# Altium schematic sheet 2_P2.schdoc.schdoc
size 309 x 223 mm; Symbol: Sheet-Symbol_A4; Device: Sheet-Symbol_A4; Company: Sai Automations; Drawed: EasyEDA Pro; Reviewed: EasyEDA Pro; Version: V0.1; Page Size: A4; @Project Name: SHA-PCB V1.1; @Page Count: 2; @Update Date: 2024-07-18; @Create Date: 2024-01-13; @Schematic Name: Schematic1; Part Number: JLCPCB-002; @Page No: 2; @Page Name: P2
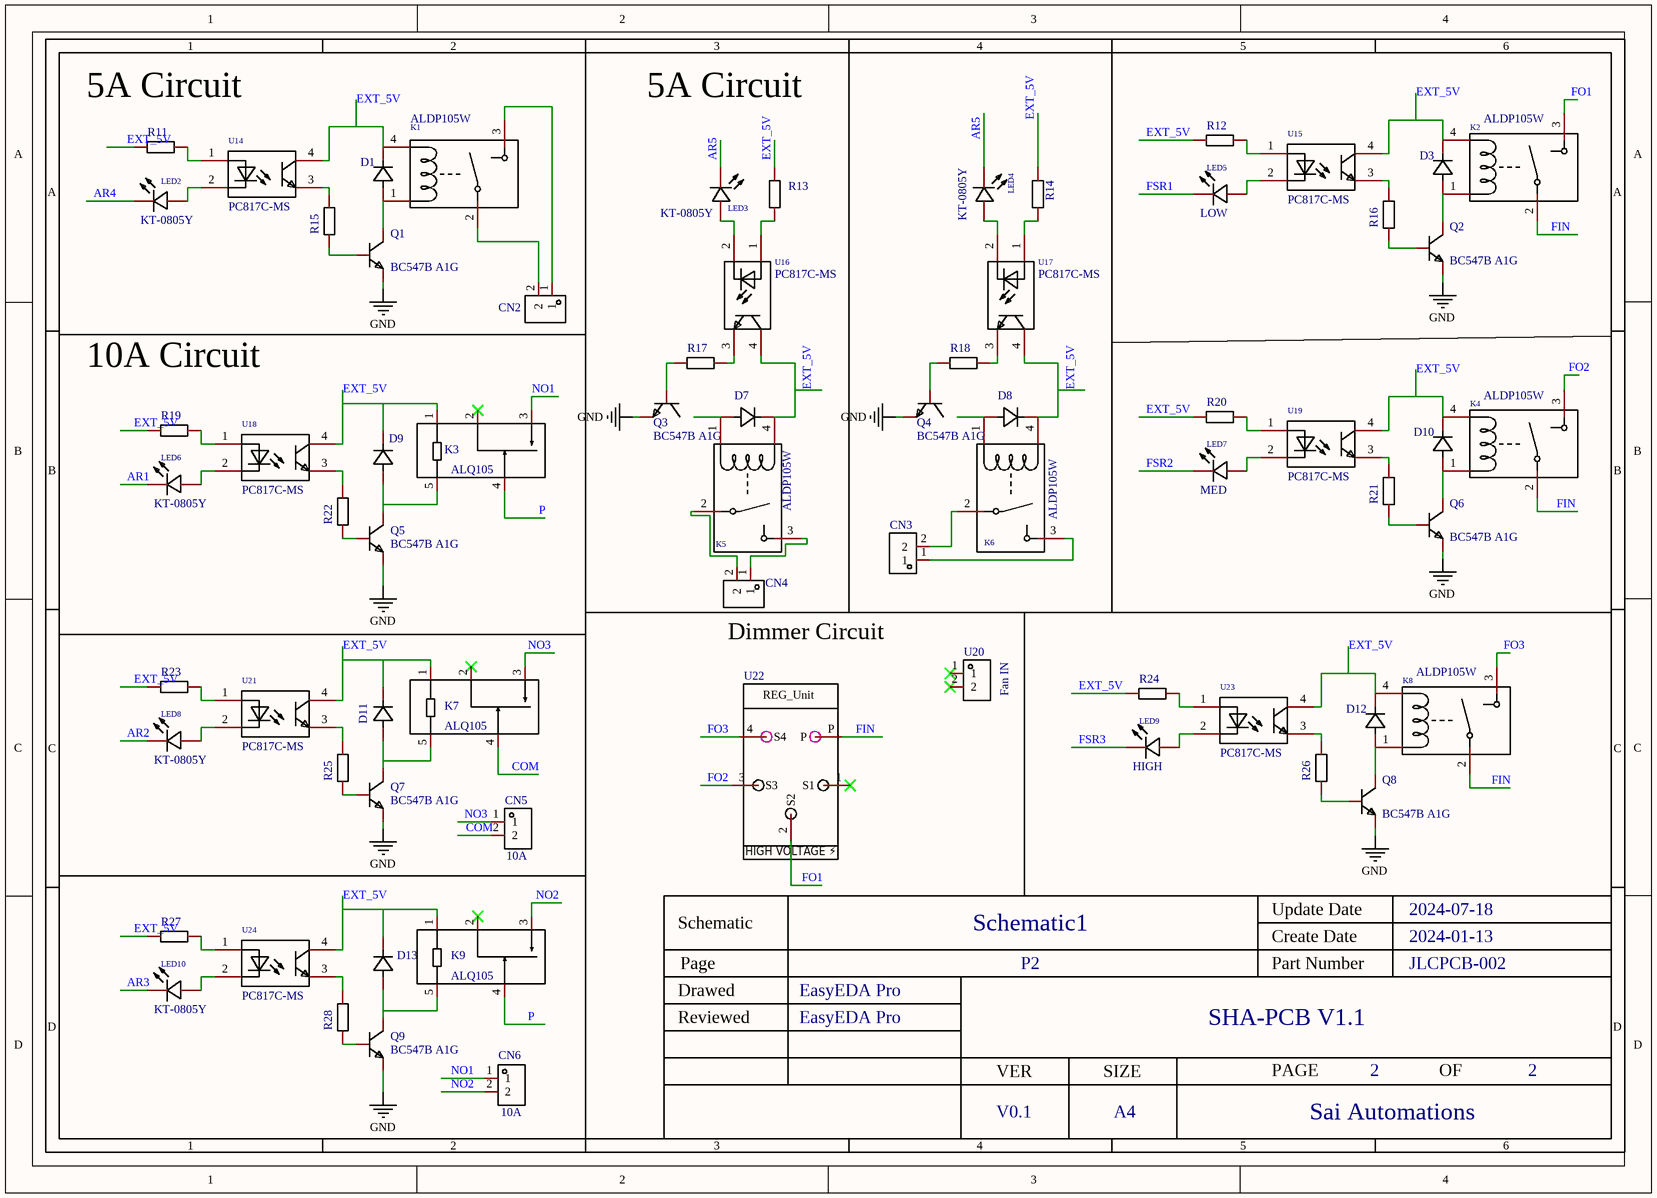
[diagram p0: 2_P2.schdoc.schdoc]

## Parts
CN2  XY2500R-G-3.5-2P  [CONN-TH_XY2500R-G-3.5-2P]  (value not drawn)
CN3  XY2500R-G-3.5-2P  [CONN-TH_XY2500R-G-3.5-2P]  (value not drawn)
CN4  XY2500R-G-3.5-2P  [CONN-TH_XY2500R-G-3.5-2P]  (value not drawn)
CN5  10A  [CONN-TH_2P-P5.08_XY2500R-D5.08-2P]
CN6  10A  [CONN-TH_XY2500R-G-3.5-2P]
D1  1N4007  [SMA_L4.4-W2.8-LS5.4-RD]  (value not drawn)
D3  1N4007  [SMA_L4.4-W2.8-LS5.4-RD]  (value not drawn)
D7  1N4007  [SMA_L4.4-W2.8-LS5.4-RD]  (value not drawn)
D8  1N4007  [SMA_L4.4-W2.8-LS5.4-RD]  (value not drawn)
D9  1N4007  [SMA_L4.4-W2.8-LS5.4-RD]  (value not drawn)
D10  1N4007  [SMA_L4.4-W2.8-LS5.4-RD]  (value not drawn)
D11  1N4007  [SMA_L4.4-W2.8-LS5.4-RD]  (value not drawn)
D12  1N4007  [SMA_L4.4-W2.8-LS5.4-RD]  (value not drawn)
D13  1N4007  [SMA_L4.4-W2.8-LS5.4-RD]  (value not drawn)
K1  ALDP105W  [RELAY-TH_ALDP1XXW]
K2  ALDP105W  [RELAY-TH_ALDP1XXW]
K3  ALQ105  [RELAY-TH_ALQ1XX]
K4  ALDP105W  [RELAY-TH_ALDP1XXW]
K5  ALDP105W  [RELAY-TH_ALDP1XXW]
K6  ALDP105W  [RELAY-TH_ALDP1XXW]
K7  ALQ105  [RELAY-TH_ALQ1XX]
K8  ALDP105W  [RELAY-TH_ALDP1XXW]
K9  ALQ105  [RELAY-TH_ALQ1XX]
LED2  KT-0805Y  [LED0805-R-RD]
LED3  KT-0805Y  [LED0805-R-RD]
LED4  KT-0805Y  [LED0805-R-RD]
LED5  LOW  [LED0805-R-RD]
LED6  KT-0805Y  [LED0805-R-RD]
LED7  MED  [LED0805-R-RD]
LED8  KT-0805Y  [LED0805-R-RD]
LED9  HIGH  [LED0805-R-RD]
LED10  KT-0805Y  [LED0805-R-RD]
Q1  BC547B A1G  [SOT-23_L2.9-W1.3-P1.90-LS2.4-BR]
Q2  BC547B A1G  [SOT-23_L2.9-W1.3-P1.90-LS2.4-BR]
Q3  BC547B A1G  [SOT-23_L2.9-W1.3-P1.90-LS2.4-BR]
Q4  BC547B A1G  [SOT-23_L2.9-W1.3-P1.90-LS2.4-BR]
Q5  BC547B A1G  [SOT-23_L2.9-W1.3-P1.90-LS2.4-BR]
Q6  BC547B A1G  [SOT-23_L2.9-W1.3-P1.90-LS2.4-BR]
Q7  BC547B A1G  [SOT-23_L2.9-W1.3-P1.90-LS2.4-BR]
Q8  BC547B A1G  [SOT-23_L2.9-W1.3-P1.90-LS2.4-BR]
Q9  BC547B A1G  [SOT-23_L2.9-W1.3-P1.90-LS2.4-BR]
R11  1kΩ  [R0402]  (value not drawn)
R12  1kΩ  [R0402]  (value not drawn)
R13  1kΩ  [R0402]  (value not drawn)
R14  1kΩ  [R0402]  (value not drawn)
R15  1kΩ  [R0402]  (value not drawn)
R16  1kΩ  [R0402]  (value not drawn)
R17  1kΩ  [R0402]  (value not drawn)
R18  1kΩ  [R0402]  (value not drawn)
R19  1kΩ  [R0402]  (value not drawn)
R20  1kΩ  [R0402]  (value not drawn)
R21  1kΩ  [R0402]  (value not drawn)
R22  1kΩ  [R0402]  (value not drawn)
R23  1kΩ  [R0402]  (value not drawn)
R24  1kΩ  [R0402]  (value not drawn)
R25  1kΩ  [R0402]  (value not drawn)
R26  1kΩ  [R0402]  (value not drawn)
R27  1kΩ  [R0402]  (value not drawn)
R28  1kΩ  [R0402]  (value not drawn)
U14  PC817C-MS  [SOP-4_L6.5-W4.6-P2.54-LS10.0]
U15  PC817C-MS  [SOP-4_L6.5-W4.6-P2.54-LS10.0]
U16  PC817C-MS  [SOP-4_L6.5-W4.6-P2.54-LS10.0]
U17  PC817C-MS  [SOP-4_L6.5-W4.6-P2.54-LS10.0]
U18  PC817C-MS  [SOP-4_L6.5-W4.6-P2.54-LS10.0]
U19  PC817C-MS  [SOP-4_L6.5-W4.6-P2.54-LS10.0]
U20  Fan IN  [CONN-TH_2P-P5.08_DB128L-5.08-2P]
U21  PC817C-MS  [SOP-4_L6.5-W4.6-P2.54-LS10.0]
U22  REG  [REG 1]  (value not drawn)
U23  PC817C-MS  [SOP-4_L6.5-W4.6-P2.54-LS10.0]
U24  PC817C-MS  [SOP-4_L6.5-W4.6-P2.54-LS10.0]

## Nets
GND: Q1.2(E) Q2.2(E) Q3.2(E) Q4.2(E) Q5.2(E) Q6.2(E) Q7.2(E) Q8.2(E) Q9.2(E)
AR1: LED6.2(-)
AR2: LED8.2(-)
AR3: LED10.2(-)
AR4: LED2.2(-)
AR5: LED3.2(-) LED4.2(-)
COM: CN5.2 K7.4(N.C.)
EXT_5V: D1.1(K) D3.1(K) D7.1(K) D8.1(K) D9.1(K) D10.1(K) D11.1(K) D12.1(K) D13.1(K) K1.4 K2.4 K3.1 K4.4 K5.4 K6.4 K7.1 K8.4 K9.1 R11.2 R12.2 R13.2 R14.2 R19.2 R20.2 R23.2 R24.2 R27.2 U14.4(COL) U15.4(COL) U16.4(COL) U17.4(COL) U18.4(COL) U19.4(COL) U21.4(COL) U23.4(COL) U24.4(COL)
FIN: K2.2 K4.2 K8.2 U22.P
FO1: K2.3 U22.2(S2)
FO2: K4.3 U22.3(S3)
FO3: K8.3 U22.4(S4)
FSR1: LED5.2(-)
FSR2: LED7.2(-)
FSR3: LED9.2(-)
NO1: CN6.1 K3.3(N.O.)
NO2: CN6.2 K9.3(N.O.)
NO3: CN5.1 K7.3(N.O.)
P: K3.4(N.C.) K9.4(N.C.)
NetCN2_1: CN2.1 K1.3
NetCN2_2: CN2.2 K1.2
NetCN3_1: CN3.1 K6.3
NetCN3_2: CN3.2 K6.2
NetCN4_1: CN4.1 K5.3
NetCN4_2: CN4.2 K5.2
NetD1_2: D1.2(A) K1.1 Q1.3(C)
NetD3_2: D3.2(A) K2.1 Q2.3(C)
NetD7_2: D7.2(A) K5.1
NetD8_2: D8.2(A) K6.1
NetD9_2: D9.2(A) K3.5 Q5.3(C)
NetD10_2: D10.2(A) K4.1 Q6.3(C)
NetD11_2: D11.2(A) K7.5 Q7.3(C)
NetD12_2: D12.2(A) K8.1 Q8.3(C)
NetD13_2: D13.2(A) K9.5 Q9.3(C)
NetLED2_1: LED2.1(+) U14.2(CAT)
NetLED3_1: LED3.1(+) U16.2(CAT)
NetLED4_1: LED4.1(+) U17.2(CAT)
NetLED5_1: LED5.1(+) U15.2(CAT)
NetLED6_1: LED6.1(+) U18.2(CAT)
NetLED7_1: LED7.1(+) U19.2(CAT)
NetLED8_1: LED8.1(+) U21.2(CAT)
NetLED9_1: LED9.1(+) U23.2(CAT)
NetLED10_1: LED10.1(+) U24.2(CAT)
NetQ1_1: Q1.1(B) R15.2
NetQ2_1: Q2.1(B) R16.2
NetQ3_1: Q3.1(B) R17.2
NetQ4_1: Q4.1(B) R18.2
NetQ5_1: Q5.1(B) R22.2
NetQ6_1: Q6.1(B) R21.2
NetQ7_1: Q7.1(B) R25.2
NetQ8_1: Q8.1(B) R26.2
NetQ9_1: Q9.1(B) R28.2
NetR11_1: R11.1 U14.1(AN)
NetR12_1: R12.1 U15.1(AN)
NetR13_1: R13.1 U16.1(AN)
NetR14_1: R14.1 U17.1(AN)
NetR15_1: R15.1 U14.3(EMI)
NetR16_1: R16.1 U15.3(EMI)
NetR17_1: R17.1 U16.3(EMI)
NetR18_1: R18.1 U17.3(EMI)
NetR19_1: R19.1 U18.1(AN)
NetR20_1: R20.1 U19.1(AN)
NetR21_1: R21.1 U19.3(EMI)
NetR22_1: R22.1 U18.3(EMI)
NetR23_1: R23.1 U21.1(AN)
NetR24_1: R24.1 U23.1(AN)
NetR25_1: R25.1 U21.3(EMI)
NetR26_1: R26.1 U23.3(EMI)
NetR27_1: R27.1 U24.1(AN)
NetR28_1: R28.1 U24.3(EMI)

Not connected (* = marked no-connect by the designer): K3 2(COM)*; K7 2(COM)*; K9 2(COM)*; Q3 3(C); Q4 3(C); U20 1* 2*; U22 1(S1)*

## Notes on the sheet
- 5A Circuit
- 10A Circuit
- Dimmer Circuit

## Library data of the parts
CN2-CN4 CN6 = XY2500R-G-3.5-2P: Manufacturer: XINLAIYA(新莱亚); Add into BOM: yes; Connector Type: 板端/Receptacle-Close; Structure: 1x2P; Pitch: 3.5mm; Number of PINs Per Row: 2; Current Rating (Max): 8A; Voltage Rating (Max): 300V; Description: Connector Type:板端/Receptacle-Close Structure:1x2P Pitch:3.5mm Color:Green Mounting Style:Bend Number of Pins:2P Number of Rows:1 Number of PINs Per Row:2 Current Rating (Max):8A Voltage Rating (Max):300V Contact Material:Brass Contact Plating:Tin Operatin
CN5 = XY2500R-D-5.08-2P: Manufacturer: XINLAIYA(新莱亚); Add into BOM: yes; Connector Type: 板端/Receptacle-Close; Structure: 1x2P; Pitch: 5.08mm; Number of PINs Per Row: 2; Current Rating (Max): 15A; Voltage Rating (Max): 300V; Description: Connector Type:板端/Receptacle-Close Structure:1x2P Pitch:5.08mm Color:Green Mounting Style:Bend Number of Pins:2P Number of Rows:1 Number of PINs Per Row:2 Current Rating (Max):15A Voltage Rating (Max):300V Contact Material:Brass Contact Plating:Tin
D1 D3 D7-D13 = 1N4007: Symbol: D_1N4007; Add into BOM: yes
K1 K2 K4-K6 K8 = ALDP105W: Manufacturer: PANASONIC(松下); Add into BOM: yes; Description: Contact Form:- Coil Type:
K3 K7 K9 = ALQ105: Manufacturer: PANASONIC(松下); Add into BOM: yes; Coil Voltage: 5V; Contact Form: 一组转换:1C(SPDT-转换); Maximum Switching Voltage: 250V@AC; Maximum Switching Current: 10A; Operate Time: 20ms; Description: Coil Voltage:5V Contact Form:一组转换:1C(SPDT-转换) Pin Number:- Contact Rating:- Maximum Switching Voltage:250V@AC Contact Material:AgNi Maximum Switching Current:10A Coil Type: Coil Resistance:- Contact Resistance:- Operate Time:20ms Release Time:20ms Operati
LED2-LED10 = KT-0805Y: Manufacturer: KENTO; Symbol: 17-21SUYC/TR8; Add into BOM: yes; Emitted Color: Yellow; Description: Emitted Color:Yellow Diode Configuration:- Forward Current:- Power Dissipation:- Lens Color:- Dominant Wavelength:- Dominant Wavelength:- Peak Wavelength:- Color Temperature:- Color Temperature:- Viewing Angle:- Mounting Sytle:- Operating Temperature:- Op
Q1-Q9 = S8050_NPN: Symbol: NPN; Add into BOM: yes
R11-R28 = RC0402FR-071KL: Manufacturer: YAGEO(国巨); Add into BOM: yes; Tolerance: ±1%; Temperature Coefficient: ±100ppm/℃; Description: Type:Thick Film Resistors Resistance: Tolerance:±1% Tolerance:±1% Power(Watts): Temperature Coefficient:±100ppm/℃ Temperature Coefficient:±100ppm/℃ Overload Voltage (Max): Operating Temperature Range:-55℃~+155℃ Operating Temperature Range:-55℃~+155℃
U14-U19 U21 U23 U24 = PC817C-MS: Manufacturer: MSKSEMI(美森科); Add into BOM: yes; Output Type: 光电三极管; Forward Voltage: 1.2V; Output Current: 50mA; Reverse Voltage: 6V; Receiving End Voltage: 35V; Number of Outputs: 1; Description: Output Type:光电三极管 Forward Voltage:1.2V Output Current:50mA Reverse Voltage:6V Receiving End Voltage:35V Number of Outputs:1
U20 = DB128L-5.08-2P-GN-S: Manufacturer: DORABO(地博电气); Add into BOM: yes; Structure: 1x2P; Pitch: 5.08mm; Current Rating (Max): 18A; Voltage Rating (Max): 250V; Wire Gauge - AWG: 12~30; Wire Gauge - mm2: 2.5; Number of PINs Per Row: 2; Description: Structure:1x2P Pitch:5.08mm Color:Green Mounting Style:Straight Current Rating (Max):18A Voltage Rating (Max):250V Number of Pins:2P Number of Rows:1 Wire Gauge - AWG:12~30 Wire Gauge - AWG:12~30 Wire Gauge - mm2:2.5 Wire Gauge - mm2:2.5 Number of PINs Pe
U22 = REG: Add into BOM: yes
